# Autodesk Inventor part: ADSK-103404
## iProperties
Shininess: 0.0
Created: 2000-11
Part Number: ADSK-103404
Document SubType Name: Modeling
Stock Number: ADSK-103404
Density: 1 g/cm^3
Density: 0.0
Volumn: 0.0
Area: 0.0
PropertySet Name: Model Information
Control State: 0
Master: False
Checked Out: False
Author: gao
